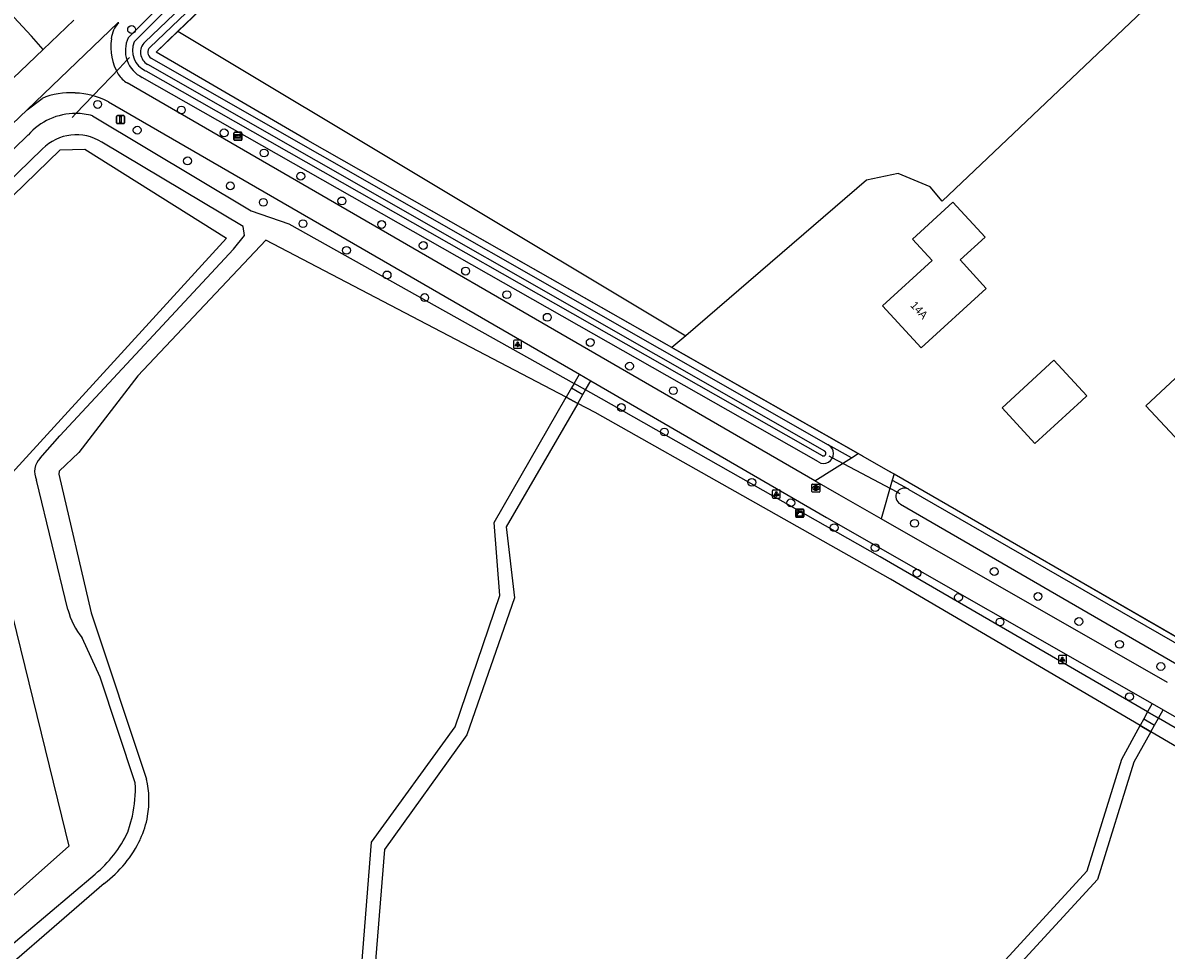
# Model space of a CAD drawing. Extents: x 157154 to 159278, y 385000 to 386650.
# Drawn here: x 157593.2 to 157736, y 385983.3 to 386099.1 of the extents above; entities that cross this region are included whole.
import ezdxf

# ---------------------------------------------------------------- set-up
doc = ezdxf.new("R2010")
doc.units = 0
for name, color, linetype in [('IMGEO_Boom', 7, 'Continuous'), ('IMGEO_Bouwland', 7, 'Continuous'), ('IMGEO_Duiker', 7, 'Continuous'), ('IMGEO_Gemengd_bos', 7, 'Continuous'), ('IMGEO_Grasland_overig', 7, 'Continuous'), ('IMGEO_Groenvoorziening', 7, 'Continuous'), ('IMGEO_Hek', 7, 'Continuous'), ('IMGEO_Kast', 7, 'Continuous'), ('IMGEO_Lichtpunt', 7, 'Continuous'), ('IMGEO_Pand', 7, 'Continuous'), ('IMGEO_Pand_nummerreeks', 7, 'Continuous'), ('IMGEO_Rijbaan_lokaal_gesloten', 7, 'Continuous'), ('IMGEO_Rijbaan_lokaal_open', 7, 'Continuous'), ('IMGEO_Rioolput', 7, 'Continuous'), ('IMGEO_Verkeersbordpaal', 7, 'Continuous'), ('IMGEO_Voetpad_gesloten', 7, 'Continuous'), ('IMGEO_Voetpad_open', 7, 'Continuous'), ('IMGEO_Waterloop', 7, 'Continuous'), ('IMGEO_Wegwijzer', 7, 'Continuous')]:
    doc.layers.add(name, color=color, linetype=linetype)

msp = doc.modelspace()

# ---------------------------------------------------------------- linework, layer by layer
at = {"layer": 'IMGEO_Boom'}
for centre in [(157606.73, 386098.31), (157602.5, 386088.95), (157612.94, 386088.25), (157607.43, 386085.73), (157618.29, 386085.39), (157623.28, 386082.88), (157613.72, 386081.89), (157627.86, 386079.98), (157619.06, 386078.77), (157623.18, 386076.71), (157633, 386076.89), (157628.14, 386074.05), (157637.96, 386073.95), (157643.16, 386071.32), (157633.58, 386070.71), (157648.45, 386068.12), (157638.64, 386067.64), (157653.61, 386065.18), (157643.33, 386064.81), (157658.65, 386062.35), (157664.02, 386059.2), (157668.93, 386056.24), (157674.4, 386053.17), (157667.9, 386051.07), (157673.27, 386048.01), (157684.2, 386041.72), (157689.07, 386039.15), (157694.49, 386036.06), (157704.53, 386036.59), (157699.61, 386033.56), (157704.83, 386030.37), (157714.48, 386030.57), (157710.01, 386027.33), (157719.94, 386027.46), (157715.2, 386024.27), (157725.05, 386024.32), (157730.13, 386021.48), (157735.29, 386018.7), (157731.37, 386014.93)]:
    msp.add_circle(centre, 0.489, dxfattribs=at)
at = {"layer": 'IMGEO_Bouwland'}
for points in [[(157612.51, 386098.09), (157698, 386179.78), (157700.88, 386182.53), (157771.24, 386250), (157822.18, 386298.66), (157824.74, 386301.1), (157950.55, 386421.28), (158000, 386427.78), (158113.15, 386441.94), (158120.69, 386442.92), (158214.68, 386455.16), (158223.4, 386455.79), (158232.84, 386455.66), (158237.98, 386453.24)], [(157778.82, 386116.38), (157777.95, 386115.55), (157775.39, 386113.12), (157774.22, 386111.95), (157771.31, 386114.76), (157772.08, 386115.54), (157772.38, 386117.69), (157772.31, 386119.08), (157771.65, 386120.26), (157770.12, 386121.1), (157768.46, 386121.55), (157766.61, 386121.2), (157765.33, 386120.33), (157764.32, 386118.56), (157764.35, 386116.27), (157765.33, 386114.6), (157766.45, 386113.36), (157756.3, 386113.56), (157751.64, 386118.34), (157707.98, 386076.86), (157706.46, 386078.63), (157702.5, 386080.31), (157698.54, 386079.47), (157675.97, 386060.01)]]:
    msp.add_lwpolyline(points, dxfattribs=at)
at = {"layer": 'IMGEO_Duiker'}
for points in [[(157606.48, 386094.81), (157606.15, 386094.47), (157605.21, 386093.49), (157601.95, 386090.08), (157599.77, 386087.81), (157599.29, 386087.31)], [(157702.71, 386040.3), (157702.35, 386040.49), (157694.25, 386044.77), (157693.87, 386044.97)]]:
    msp.add_lwpolyline(points, dxfattribs=at)
at = {"layer": 'IMGEO_Gemengd_bos'}
msp.add_lwpolyline([(157543.9, 386034.12), (157544.83, 386033.82), (157546.23, 386033.37), (157552.49, 386039.41), (157574.16, 386060.33), (157597.82, 386083.26), (157600.88, 386083.37), (157618.6, 386072.25), (157588.24, 386039.03), (157590.26, 386031.28), (157597.98, 386000), (157598.9, 385996.27), (157574.27, 385974.36), (157562.9, 385964.41)], dxfattribs=at)
at = {"layer": 'IMGEO_Grasland_overig'}
for points in [[(157674.23, 386058.56), (157628.74, 386084.45), (157609.8, 386095.49), (157612.51, 386098.09)], [(157612.51, 386098.09), (157675.97, 386060.01)], [(157675.97, 386060.01), (157674.23, 386058.56)]]:
    msp.add_lwpolyline(points, dxfattribs=at)
at = {"layer": 'IMGEO_Groenvoorziening'}
for points in [[(158210.12, 386455.41), (158155.11, 386448.01), (158053.81, 386435.27), (157950.19, 386421.73), (157949.83, 386421.56), (157609.02, 386096.07)], [(157606.31, 386097.29), (157612.05, 386103.08), (157905.53, 386383.09), (157936.81, 386413.37), (157944.27, 386420.38), (157947.56, 386423.48)], [(157609.19, 386094.75), (157693.75, 386046.41)], [(157692.52, 386044.27), (157608.07, 386092.33)], [(157674.23, 386058.56), (157697.5, 386045.31)], [(157696.67, 386044.79), (157693.75, 386046.41)], [(157701.73, 386041.99), (157703.72, 386040.89)], [(157701.96, 386042.77), (157740.31, 386020.61)]]:
    msp.add_lwpolyline(points, dxfattribs=at)
for centre, radius, start, end in [((157609.67, 386095.69), 3.72, 154.5346, 244.5592), ((157609.58, 386095.47), 0.825, 132.8312, 241.1639), ((157693.15, 386045.33), 1.24, 239.477, 60.7573)]:
    msp.add_arc(centre, radius, start, end, dxfattribs=at)
at = {"layer": 'IMGEO_Hek'}
for points in [[(157698.08, 386044.98), (157628.74, 386084.45), (157609.8, 386095.49), (157698, 386179.78)], [(157543.9, 386034.12), (157544.83, 386033.82), (157546.23, 386033.37), (157552.49, 386039.41), (157574.16, 386060.33), (157597.82, 386083.26), (157600.88, 386083.37), (157618.6, 386072.25), (157588.24, 386039.03), (157590.26, 386031.28), (157597.98, 386000), (157598.9, 385996.27), (157574.27, 385974.36), (157562.9, 385964.41)], [(157740.31, 386020.61), (157701.49, 386043.04)]]:
    msp.add_lwpolyline(points, dxfattribs=at)
at = {"layer": 'IMGEO_Kast'}
for p, q in [((157689.69, 386037.44), (157689.69, 386038.28)), ((157689.69, 386038.28), (157689.69, 386037.44)), ((157689.77, 386038.36), (157690.61, 386038.36)), ((157690.61, 386038.36), (157689.77, 386038.36)), ((157690.62, 386037.36), (157689.78, 386037.36)), ((157689.78, 386037.36), (157690.62, 386037.36)), ((157690.69, 386038.29), (157690.69, 386037.45)), ((157690.69, 386037.45), (157690.69, 386038.29))]:
    msp.add_line(p, q, dxfattribs=at)
for points in [[(157689.89, 386038.15), (157690.49, 386038.15), (157690.49, 386038.07), (157689.89, 386038.07), (157689.89, 386038.15)], [(157689.89, 386037.98), (157690.49, 386037.98), (157690.49, 386037.49), (157689.89, 386037.49), (157689.89, 386037.98)]]:
    msp.add_lwpolyline(points, dxfattribs=at)
msp.add_circle((157689.97, 386037.83), 0.0377, dxfattribs=at)
for centre, start, end in [((157689.77, 386038.28), 92.4484, 184.2845), ((157689.77, 386038.28), 92.4484, 184.2845), ((157689.77, 386037.44), 182.4484, 274.2845), ((157689.77, 386037.44), 182.4484, 274.2845), ((157690.61, 386038.28), 2.4484, 94.2845), ((157690.61, 386038.28), 2.4484, 94.2845), ((157690.61, 386037.44), 272.4484, 4.2845), ((157690.61, 386037.44), 272.4484, 4.2845)]:
    msp.add_arc(centre, 0.0779, start, end, dxfattribs=at)
at = {"layer": 'IMGEO_Lichtpunt'}
for p, q in [((157654.45, 386059.38), (157654.45, 386058.57)), ((157654.45, 386059.38), (157654.45, 386058.57)), ((157655.35, 386059.47), (157654.54, 386059.47)), ((157655.35, 386059.47), (157654.54, 386059.47)), ((157655.44, 386058.57), (157655.44, 386059.38)), ((157655.44, 386058.57), (157655.44, 386059.38)), ((157654.54, 386058.47), (157655.35, 386058.47)), ((157654.54, 386058.47), (157655.35, 386058.47)), ((157686.76, 386040.67), (157686.76, 386039.86)), ((157686.76, 386040.67), (157686.76, 386039.86)), ((157687.66, 386040.76), (157686.86, 386040.76)), ((157687.66, 386040.76), (157686.86, 386040.76)), ((157687.76, 386039.86), (157687.76, 386040.67)), ((157687.76, 386039.86), (157687.76, 386040.67)), ((157686.86, 386039.76), (157687.66, 386039.76)), ((157686.86, 386039.76), (157687.66, 386039.76)), ((157722.49, 386019.99), (157722.49, 386019.18)), ((157722.49, 386019.99), (157722.49, 386019.18)), ((157723.4, 386020.08), (157722.59, 386020.08)), ((157723.4, 386020.08), (157722.59, 386020.08)), ((157723.49, 386019.18), (157723.49, 386019.99)), ((157723.49, 386019.18), (157723.49, 386019.99)), ((157722.59, 386019.08), (157723.4, 386019.08)), ((157722.59, 386019.08), (157723.4, 386019.08))]:
    msp.add_line(p, q, dxfattribs=at)
for points in [[(157654.82, 386059.04), (157654.86, 386059.01), (157654.67, 386058.75), (157654.63, 386058.78), (157654.82, 386059.04)], [(157654.92, 386058.99), (157654.97, 386058.99), (157654.97, 386058.67), (157654.92, 386058.67), (157654.92, 386058.99)], [(157655.03, 386059.01), (157655.07, 386059.04), (157655.26, 386058.78), (157655.22, 386058.75), (157655.03, 386059.01)], [(157687.14, 386040.33), (157687.17, 386040.3), (157686.99, 386040.04), (157686.95, 386040.07), (157687.14, 386040.33)], [(157687.24, 386040.28), (157687.29, 386040.28), (157687.29, 386039.96), (157687.24, 386039.96), (157687.24, 386040.28)], [(157687.35, 386040.3), (157687.39, 386040.33), (157687.57, 386040.07), (157687.53, 386040.04), (157687.35, 386040.3)], [(157722.87, 386019.65), (157722.91, 386019.62), (157722.72, 386019.36), (157722.68, 386019.39), (157722.87, 386019.65)], [(157722.97, 386019.6), (157723.02, 386019.6), (157723.02, 386019.28), (157722.97, 386019.28), (157722.97, 386019.6)], [(157723.08, 386019.62), (157723.12, 386019.65), (157723.31, 386019.39), (157723.27, 386019.36), (157723.08, 386019.62)]]:
    msp.add_lwpolyline(points, dxfattribs=at)
for centre in [(157654.95, 386059.17), (157687.26, 386040.46), (157722.99, 386019.78)]:
    msp.add_circle(centre, 0.0994, dxfattribs=at)
for centre, start, end in [((157654.54, 386059.38), 90, 180), ((157654.54, 386059.38), 90, 180), ((157654.54, 386058.57), 180, 270), ((157654.54, 386058.57), 180, 270), ((157655.35, 386059.38), 0, 90), ((157655.35, 386059.38), 0, 90), ((157655.35, 386058.57), 270, 0), ((157655.35, 386058.57), 270, 360), ((157686.86, 386040.67), 90, 180), ((157686.86, 386040.67), 90, 180), ((157687.66, 386040.67), 0, 90), ((157687.66, 386040.67), 0, 90), ((157686.86, 386039.86), 180, 270), ((157686.86, 386039.86), 180, 270), ((157687.66, 386039.86), 270, 0), ((157687.66, 386039.86), 270, 360), ((157722.59, 386019.99), 90, 180), ((157722.59, 386019.99), 90, 180), ((157723.4, 386019.99), 0, 90), ((157723.4, 386019.99), 0, 90), ((157722.59, 386019.18), 180, 270), ((157722.59, 386019.18), 180, 270), ((157723.4, 386019.18), 270, 0), ((157723.4, 386019.18), 270, 360)]:
    msp.add_arc(centre, 0.0946, start, end, dxfattribs=at)
at = {"layer": 'IMGEO_Pand'}
for points in [[(157741.77, 386042.33), (157733.43, 386051.27), (157759.21, 386075.36), (157770.8, 386086.2), (157784.41, 386071.6), (157781.41, 386068.8), (157779.91, 386067.41), (157769.18, 386057.41), (157767.6, 386059.12), (157765.18, 386056.82), (157761.5, 386060.77), (157753.05, 386052.87), (157742.12, 386042.66)], [(157709.32, 386076.75), (157713.34, 386072.36), (157710.23, 386069.52), (157713.49, 386065.96), (157705.35, 386058.51), (157700.52, 386063.78), (157706.72, 386069.46), (157704.27, 386072.12), (157709.32, 386076.75)], [(157721.91, 386056.99), (157726.03, 386052.52), (157725.36, 386051.91), (157719.57, 386046.57), (157715.45, 386051.03), (157721.91, 386056.99)]]:
    msp.add_lwpolyline(points, dxfattribs=at)
at = {"layer": 'IMGEO_Rijbaan_lokaal_gesloten'}
for points in [[(157692.09, 386041.92), (157696.67, 386044.79)], [(157696.67, 386044.79), (157697.5, 386045.31)], [(157697.5, 386045.31), (157698.08, 386044.98), (157701.49, 386043.04), (157701.96, 386042.77)], [(157700.34, 386037.17), (157695.11, 386040.17), (157692.09, 386041.92)], [(157701.73, 386041.99), (157700.34, 386037.17)], [(157701.96, 386042.77), (157701.73, 386041.99)]]:
    msp.add_lwpolyline(points, dxfattribs=at)
at = {"layer": 'IMGEO_Rijbaan_lokaal_open'}
for points in [[(157595.68, 386095.83), (157594.21, 386097.48), (157522.68, 386174.47), (157474.02, 386226.12), (157470.7, 386229.29), (157468.15, 386231.3), (157443.08, 386247.7)], [(157605.13, 386099.14), (157605.01, 386099.14), (157593.7, 386088.29)], [(157599.53, 386099.49), (157595.68, 386095.83)], [(157524, 386027.27), (157595.68, 386095.83)], [(157692.09, 386041.92), (157606.18, 386091.63)], [(157593.7, 386088.29), (157595.55, 386089.68)], [(157603.83, 386089.29), (157662.66, 386055.23)], [(157540.48, 386037.39), (157593.7, 386088.29)], [(157662.66, 386055.23), (157664.09, 386054.4)], [(157664.09, 386054.4), (157693.54, 386037.34), (157734.19, 386014.09)], [(157736.12, 386016.7), (157700.34, 386037.17)], [(157734.19, 386014.09), (157735.58, 386013.29)], [(157735.58, 386013.29), (157770.68, 385993.21), (157787.43, 385983.8)]]:
    msp.add_lwpolyline(points, dxfattribs=at)
for centre, radius, start, end in [((157607.28, 386096.93), 3.09, 134.0318, 176.1436), ((157610.78, 386096.13), 6.65, 171.3298, 210.8253), ((157608.13, 386094.74), 3.67, 213.3289, 237.8664), ((157598.98, 386081.88), 8.53, 85.3927, 113.7395), ((157599.36, 386080.68), 9.7, 62.5457, 88.1812)]:
    msp.add_arc(centre, radius, start, end, dxfattribs=at)
at = {"layer": 'IMGEO_Rioolput'}
for p, q in [((157691.71, 386040.58), (157691.71, 386041.43)), ((157691.78, 386041.51), (157692.63, 386041.51)), ((157692.71, 386041.43), (157692.71, 386040.58)), ((157692.63, 386040.51), (157691.78, 386040.51)), ((157692.22, 386040.73), (157692.19, 386040.73)), ((157692.2, 386041.29), (157692.22, 386041.29))]:
    msp.add_line(p, q, dxfattribs=at)
for points in [[(157691.71, 386040.58), (157691.71, 386041.43)], [(157691.78, 386041.51), (157692.63, 386041.51)], [(157692.71, 386041.43), (157692.71, 386040.58)], [(157692.63, 386040.51), (157691.78, 386040.51)], [(157692.3, 386041.21), (157692.04, 386041.21), (157692.04, 386040.81)], [(157692.04, 386040.81), (157692.17, 386040.81), (157692.17, 386040.97), (157692.18, 386040.97)], [(157692.22, 386041.13), (157692.17, 386041.13), (157692.17, 386041.05)], [(157692.17, 386041.05), (157692.22, 386041.05)], [(157692.23, 386040.94), (157692.3, 386040.81), (157692.44, 386040.81), (157692.37, 386040.93)]]:
    msp.add_lwpolyline(points, dxfattribs=at)
for centre, radius, start, end in [((157691.78, 386041.43), 0.0765, 91.552, 178.448), ((157691.78, 386041.43), 0.0765, 91.552, 178.448), ((157692.63, 386041.43), 0.0765, 1.552, 88.448), ((157692.63, 386041.43), 0.0765, 1.552, 88.448), ((157691.78, 386040.58), 0.0765, 181.552, 268.448), ((157691.78, 386040.58), 0.0765, 181.552, 268.448), ((157692.18, 386040.92), 0.0533, 26.0293, 88.6989), ((157692.23, 386041.03), 0.0964, 77.0061, 93.1865), ((157692.2, 386041.24), 0.19, 274.7715, 282.9687), ((157692.24, 386041.09), 0.0378, 276.6634, 79.6772), ((157692.3, 386041.1), 0.109, 350.3612, 89.416), ((157692.29, 386041.1), 0.112, 277.5842, 350.9817), ((157692.28, 386040.88), 0.108, 29.5134, 73.7905), ((157692.63, 386040.58), 0.0765, 271.552, 358.448), ((157692.63, 386040.58), 0.0765, 271.552, 358.448)]:
    msp.add_arc(centre, radius, start, end, dxfattribs=at)
for centre, major_axis, ratio, start_param, end_param in [((157692.19, 386041.01), (-0.387, 0.002), 0.722429, 4.712389, 7.853982), ((157692.22, 386041.01), (-0.39, 0.002), 0.717154, 1.570796, 4.712389)]:
    msp.add_ellipse(centre, major_axis=major_axis, ratio=ratio, start_param=start_param, end_param=end_param, dxfattribs=at)
at = {"layer": 'IMGEO_Verkeersbordpaal'}
for p, q in [((157604.86, 386086.65), (157604.86, 386087.45)), ((157604.86, 386087.45), (157604.86, 386086.65)), ((157604.96, 386087.55), (157605.75, 386087.55)), ((157605.75, 386087.55), (157604.96, 386087.55)), ((157605.85, 386087.45), (157605.85, 386086.65)), ((157605.85, 386086.65), (157605.85, 386087.45)), ((157605.75, 386086.55), (157604.96, 386086.55)), ((157604.96, 386086.55), (157605.75, 386086.55))]:
    msp.add_line(p, q, dxfattribs=at)
msp.add_lwpolyline([(157605.28, 386087.43), (157605.43, 386087.43), (157605.43, 386086.68), (157605.28, 386086.68), (157605.28, 386087.43)], dxfattribs=at)
for centre, start, end in [((157604.96, 386087.45), 90, 180), ((157604.96, 386087.45), 90, 180), ((157605.75, 386087.45), 0, 90), ((157605.75, 386087.45), 360, 90), ((157604.96, 386086.65), 180, 270), ((157604.96, 386086.65), 180, 270), ((157605.75, 386086.65), 270, 0), ((157605.75, 386086.65), 270, 0)]:
    msp.add_arc(centre, 0.1, start, end, dxfattribs=at)
at = {"layer": 'IMGEO_Voetpad_gesloten'}
for points in [[(157662, 386054.08), (157662.66, 386055.23)], [(157663.44, 386053.28), (157664.09, 386054.4)], [(157661.68, 386053.53), (157661, 386052.35), (157662.46, 386051.58), (157663.11, 386052.71)], [(157663.11, 386052.71), (157663.44, 386053.28), (157662, 386054.08), (157661.68, 386053.53)], [(157661.68, 386053.53), (157663.11, 386052.71)], [(157663.44, 386053.28), (157662, 386054.08)], [(157632.44, 385924.76), (157643.76, 385933.87), (157647.66, 385938.24), (157649.4, 385966.4), (157645.41, 385969.45), (157639.38, 385969.44), (157636.41, 385973.5), (157635.26, 385978.3), (157636.69, 385996.73), (157647.14, 386011.16), (157652.72, 386027.56), (157652.02, 386036.72), (157661, 386052.35)], [(157662.46, 386051.58), (157653.52, 386036.16), (157654.54, 386027.29), (157648.62, 386010.15), (157638.3, 385995.84), (157636.92, 385978.3), (157638, 385973.85), (157640.39, 385971.21), (157645.61, 385971.27), (157650.9, 385967.56), (157648.83, 385937.12), (157644.77, 385932.67), (157633.46, 385923.54)], [(157662.46, 386051.58), (157661, 386052.35)], [(157734.19, 386014.09), (157733.63, 386013.04)], [(157733.63, 386013.04), (157735, 386012.24)], [(157735, 386012.24), (157735.58, 386013.29)], [(157734.05, 386010.55), (157731.92, 386006.74), (157727.36, 385992.07), (157711.22, 385974.5), (157697.88, 385935.49), (157690.65, 385928.91), (157678.24, 385921.78), (157673.52, 385911.52), (157665.85, 385908.2), (157655.74, 385907.65), (157641.35, 385911.27), (157637.31, 385916.06)], [(157638.6, 385917.14), (157642.03, 385912.89), (157655.72, 385909.28), (157665.65, 385909.88), (157671.86, 385912.63), (157677.08, 385923), (157689.73, 385930.27), (157696.04, 385936.2), (157709.84, 385975.48), (157726.07, 385993.17), (157730.42, 386007.11), (157732.71, 386011.34)], [(157734.05, 386010.55), (157732.71, 386011.34)]]:
    msp.add_lwpolyline(points, dxfattribs=at)
at = {"layer": 'IMGEO_Voetpad_open'}
for points in [[(157734.5, 386011.36), (157735, 386012.24), (157733.63, 386013.04), (157733.15, 386012.15)], [(157733.15, 386012.15), (157732.71, 386011.34), (157734.05, 386010.55), (157734.5, 386011.36)], [(157733.15, 386012.15), (157734.5, 386011.36)]]:
    msp.add_lwpolyline(points, dxfattribs=at)
at = {"layer": 'IMGEO_Waterloop'}
for points in [[(157608.4, 386096.74), (157949.3, 386422.32)], [(157906.16, 386382.43), (157612.69, 386102.42), (157607.07, 386096.77)], [(157608.49, 386093.15), (157692.97, 386045.06), (157693, 386045.04), (157693.02, 386045.04), (157693.05, 386045.03), (157693.08, 386045.02), (157693.11, 386045.02), (157693.13, 386045.02), (157693.16, 386045.02), (157693.19, 386045.02), (157693.22, 386045.03), (157693.24, 386045.03), (157693.27, 386045.04), (157693.3, 386045.06), (157693.32, 386045.07), (157693.34, 386045.09), (157693.36, 386045.11), (157693.38, 386045.13), (157693.4, 386045.15), (157693.41, 386045.18), (157693.43, 386045.2), (157693.44, 386045.23), (157693.45, 386045.25), (157693.45, 386045.28), (157693.46, 386045.31), (157693.46, 386045.34), (157693.46, 386045.37), (157693.45, 386045.39), (157693.45, 386045.42), (157693.44, 386045.45), (157693.43, 386045.47), (157693.41, 386045.5), (157693.4, 386045.52), (157693.38, 386045.55), (157693.36, 386045.57), (157693.34, 386045.59), (157693.32, 386045.6), (157693.3, 386045.62), (157608.74, 386093.95)], [(157601.83, 386087.52), (157621.67, 386075.67), (157626.37, 386074.01), (157662, 386054.08)], [(157542.42, 386035.37), (157555.14, 386047.38), (157593.8, 386085.13)], [(157595.31, 386044.75), (157597.78, 386047.55), (157619.48, 386070.87), (157620.83, 386072.56), (157620.66, 386073.68), (157603, 386084.23)], [(157595.6, 386083.39), (157556.52, 386045.35), (157543.9, 386034.12)], [(157661, 386052.35), (157623.51, 386072), (157607.5, 386055.01), (157600.15, 386045.45), (157597.7, 386043.13), (157597.65, 386042.72), (157601.68, 386025.42), (157608.61, 386004.61)], [(157733.63, 386013.04), (157700.25, 386032.41), (157665.42, 386052.17), (157663.44, 386053.28)], [(157732.71, 386011.34), (157701.52, 386029.62), (157664.63, 386050.45), (157662.46, 386051.58)], [(157598.78, 386025.82), (157594.84, 386042.01)], [(157703.72, 386040.89), (157703.81, 386040.84), (157739.78, 386020.11)], [(157702.76, 386039.01), (157738.07, 386018.52)], [(157607.19, 386004.16), (157602.79, 386017.36), (157600.57, 386022.28)], [(157785.28, 385983.06), (157756.09, 386000), (157735, 386012.24)], [(157783.64, 385981.83), (157752.06, 386000), (157734.05, 386010.55)], [(157606.25, 385998.01), (157606.83, 386000)], [(157603.3, 385991.6), (157585.49, 385976.16), (157579.81, 385974.73), (157574.04, 385969), (157568.14, 385964.06), (157566.54, 385965.53), (157573.64, 385971.91), (157579.3, 385976.92), (157584.41, 385977.74), (157602.17, 385992.74)]]:
    msp.add_lwpolyline(points, dxfattribs=at)
for centre, radius, start, end in [((157609.66, 386095.69), 2.81, 157.4677, 245.227), ((157609.58, 386095.47), 1.74, 133.0767, 240.9102), ((157599.71, 386079.97), 7.84, 89.5479, 138.898), ((157599.72, 386079.99), 7.83, 74.2939, 89.5937), ((157599.82, 386079.26), 5.9, 57.3995, 135.6663), ((157597.08, 386043.04), 2.46, 135.8368, 204.7649), ((157703.25, 386039.95), 1.06, 148.8239, 241.824), ((157703.26, 386039.94), 1.06, 63.793, 148.8141), ((157607.53, 386028.01), 9.02, 194.0774, 219.441), ((157597.27, 386002.02), 11.63, 349.9997, 12.8819), ((157590.97, 386003.5), 16.24, 347.56, 2.3197), ((157597.27, 386002.04), 11.64, 335.1519, 349.9277), ((157592.31, 386004.59), 15.41, 309.7846, 334.752), ((157594.92, 386003.07), 14.2, 306.1537, 335.3384)]:
    msp.add_arc(centre, radius, start, end, dxfattribs=at)
at = {"layer": 'IMGEO_Wegwijzer'}
for p, q in [((157619.52, 386084.57), (157619.52, 386085.37)), ((157619.52, 386085.37), (157619.52, 386084.57)), ((157619.62, 386085.47), (157620.41, 386085.47)), ((157620.41, 386085.47), (157619.62, 386085.47)), ((157620.41, 386084.47), (157619.62, 386084.47)), ((157619.62, 386084.47), (157620.41, 386084.47)), ((157620.51, 386085.37), (157620.51, 386084.57)), ((157620.51, 386084.57), (157620.51, 386085.37))]:
    msp.add_line(p, q, dxfattribs=at)
for points in [[(157619.62, 386085.21), (157620.41, 386085.21), (157620.41, 386084.74), (157619.62, 386084.74), (157619.62, 386085.21)], [(157619.69, 386085.06), (157619.69, 386084.97), (157619.69, 386084.89), (157620.1, 386084.89), (157620.1, 386084.81), (157620.35, 386084.97), (157620.1, 386085.14), (157620.1, 386085.06), (157619.69, 386085.06)]]:
    msp.add_lwpolyline(points, dxfattribs=at)
for centre, start, end in [((157619.62, 386085.37), 90, 180), ((157619.62, 386085.37), 90, 180), ((157619.62, 386084.57), 180, 270), ((157619.62, 386084.57), 180, 270), ((157620.41, 386085.37), 0, 90), ((157620.41, 386085.37), 360, 90), ((157620.41, 386084.57), 270, 0), ((157620.41, 386084.57), 270, 0)]:
    msp.add_arc(centre, 0.1, start, end, dxfattribs=at)

# ---------------------------------------------------------------- texts
at = {"layer": 'IMGEO_Pand_nummerreeks'}
msp.add_text('14A', height=1, rotation=312.4819, dxfattribs=at).set_placement((157703.94, 386063.78))

doc.saveas('drawing.dxf')
